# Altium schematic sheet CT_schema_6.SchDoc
size 274 x 160 mm
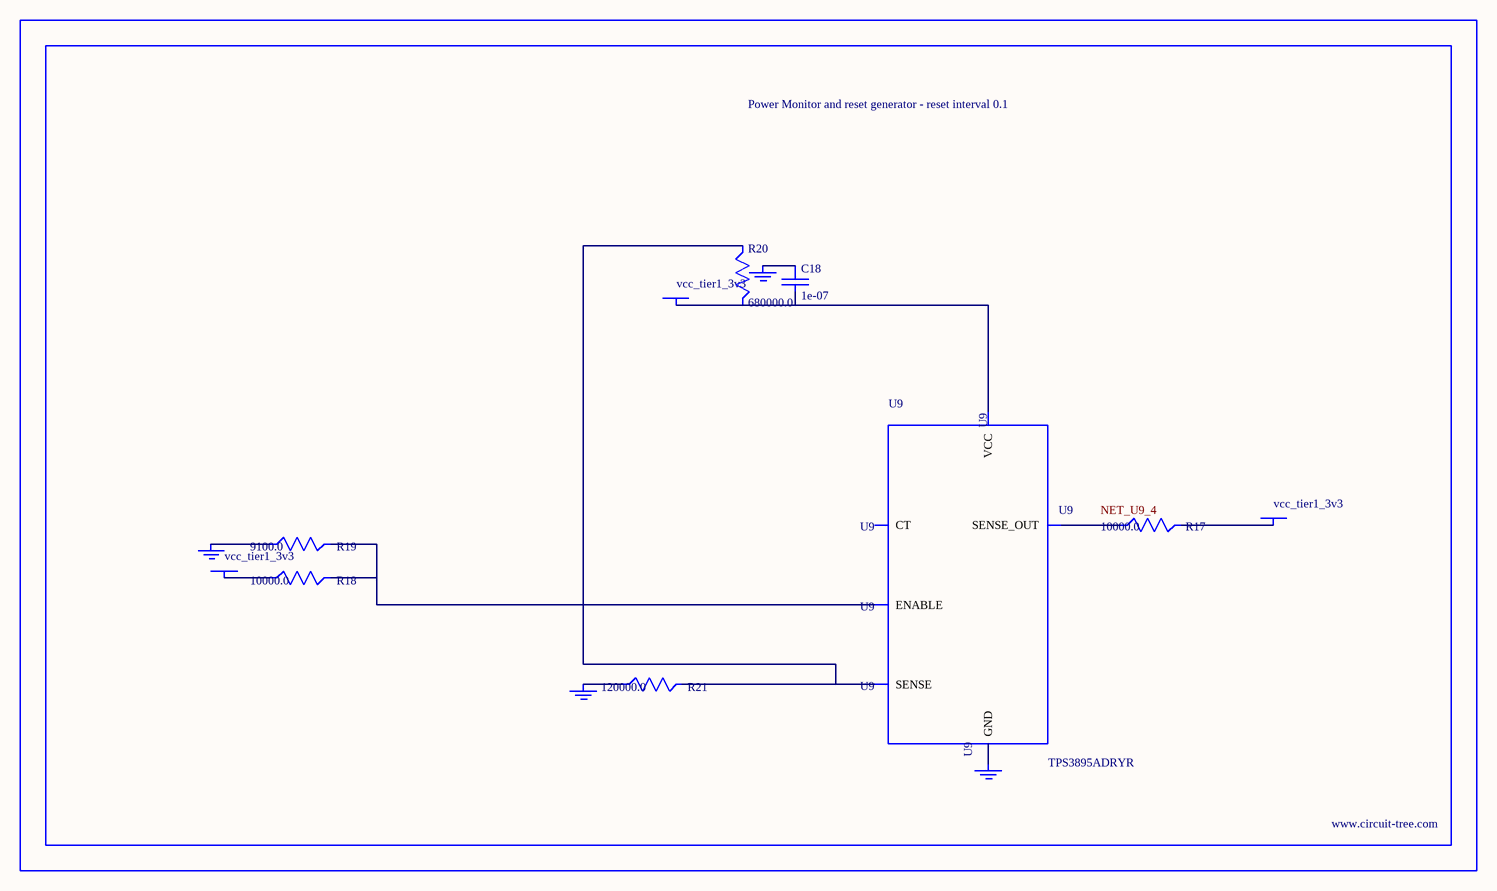
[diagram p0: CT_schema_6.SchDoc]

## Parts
BORDER5  (no value)
C18  1e-07  [C0402]
GND_INSTANCE_5_0  (no value)
GND_INSTANCE_5_1  (no value)
GND_INSTANCE_5_2  (no value)
GND_INSTANCE_5_3  (no value)
POWER_INSTANCE_5_0  vcc_tier1_3v3
POWER_INSTANCE_5_1  vcc_tier1_3v3
POWER_INSTANCE_5_2  vcc_tier1_3v3
R17  10000.0  [R0603]
R18  10000.0  [R0603]
R19  9100.0  [R0603]
R20  680000.0  [R0603]
R21  120000.0  [R0603]
U9  TPS3895ADRYR  [SON-6]

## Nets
NetC18_1: C18.1 GND_INSTANCE_5_2.0(GND)
NetC18_2: C18.2 POWER_INSTANCE_5_2.0(PWR) R20.2 U9.6(VCC)
NetGND_INSTANCE_5_0_0: GND_INSTANCE_5_0.0(GND) R19.1
NetGND_INSTANCE_5_1_0: GND_INSTANCE_5_1.0(GND) R21.1
NetGND_INSTANCE_5_3_0: GND_INSTANCE_5_3.0(GND) U9.2(GND)
NetPOWER_INSTANCE_5_0_0: POWER_INSTANCE_5_0.0(PWR) R18.1
NetPOWER_INSTANCE_5_1_0: POWER_INSTANCE_5_1.0(PWR) R17.2
NetR17_1: R17.1 U9.4(SENSE_OUT)
NetR18_2: R18.2 R19.2 U9.1(ENABLE)
NetR20_1: R20.1 R21.2 U9.3(SENSE)

Not connected (* = marked no-connect by the designer): U9 5(CT)

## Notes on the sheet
- Labels drawn without touching a wire or pin: NET_U9_4

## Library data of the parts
BORDER5 = BORDER_PAGE5
C18 = C0402C104K3RACTU
GND_INSTANCE_5_0-GND_INSTANCE_5_3 = GND
POWER_INSTANCE_5_0-POWER_INSTANCE_5_2 = PWR
R17 R18 = RC0603JR-0710KL
R19 = RC0603JR-079K1L
R20 = RC0603JR-07680KL
R21 = RC0603JR-07120KL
